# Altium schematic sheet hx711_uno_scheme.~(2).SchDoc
size A4
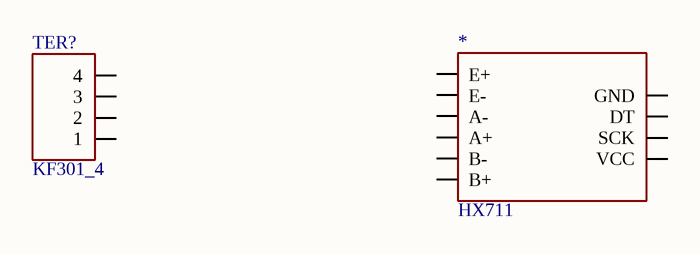
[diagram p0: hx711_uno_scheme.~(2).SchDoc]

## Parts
*  HX711  [HX711]
TER?  KF301_4  [KF304_4]

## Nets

Not connected (* = marked no-connect by the designer): * 1(E+) 2(E-) 3(A-) 4(A+) 5(B-) 6(B+) 7(GND) 8(DT) 9(SCK) 10(VCC); TER? 1 2 3 4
